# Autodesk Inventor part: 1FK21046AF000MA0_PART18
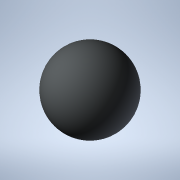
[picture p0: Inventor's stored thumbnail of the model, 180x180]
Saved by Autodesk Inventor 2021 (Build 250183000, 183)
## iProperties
Created: 2025-04
Part Number: 1FK21046AF000MA0_PART18
Material: Generic
Catalog Web Link: www.3dfindit.com
Description: -Servo synchronous motor
Document SubType Name: Modeling
Designer: psAdmin
Mass: 0.137258 g
Surface Area: 1.2868 cm^2
Volume: 0.137258 cm^3
Density: 1 g/cm^3
Appearance: PSOLRGB-212-217-219
Category: PARTsolutions
Title: 1FK21046AF000MA0_PART18
Author: Cadenas PARTsolutions
Comments: Servo synchronous motor
Sending System: PARTsolutions
Preprocessor: ST-DEVELOPER v19.3
PSOL_IDENT_0: {$CADENAS_DATA/23d-libs/siemens_ag/_cat_/1c/1f/1fk21046af000ma0.prj},216 {VTYP=3D},{NB=1FK21046AF000
PSOL_IDENT_1: MA0_PART18},{LINA=1FK21046AF000MA0_PART18},{NN=1FK21046AF000MA0_PART18},{NOPRJ=TRUE},{DATE=19.08.202
PSOL_IDENT_2: 5 14:00:28},{GEOMDATE=30.07.2025 02:02:08},{VERSION=},{LINEID=10},{WBVAR=},{WBNUMERIC=}  {NB=1FK2104
PSOL_IDENT_3: 6AF000MA0_PART18},{LINA=1FK21046AF000MA0_PART18},{KT=DUMMY},{PREVIEW=../../../_pool_/cb/72/p_d211_xx
PSOL_IDENT_4: _00434j.png},{DESCSHORT=SIMOTICS S-1FK2 HD, SINAMICS S210 3AC 400V-480V, 3.2 Nm, 3000 rpm},{DESCLONG=
PSOL_IDENT_5: SIMOTICS S-1FK2 HD servo motor M0=3.2 Nm; PN = 1 kW at nN=3000 rpm (380-480 V); PN = 0.5 kW at nN=15
PSOL_IDENT_6: 00 rpm (200-240 V); degree of protection IP64; cylindrical shaft D19x40mm; absolute encoder 22-bit +
PSOL_IDENT_7: 12-bit multiturn (encoder AM22DQC); with OCC interface; plug size M17, rotatable; SIMOTICS S-1FK2 s
PSOL_IDENT_8: ervomotorfor a wide range of uses in industrial environments. SIMOTICS S‑1FK2 servomotors are compac
PSOL_IDENT_9: t synchronous motors with a high dynamic performance that set themselves apart as a result of their
PSOL_IDENT_10: high power density, degree of protection and overload capability. The motors are available in two va
PSOL_IDENT_11: riants: as High Dynamic variant (highest dynamic performance as a result of the low intrinsic moment
PSOL_IDENT_12: of inertia for applications demanding a high dynamic performance with low moved masses) - and as Co
PSOL_IDENT_13: mpact variant (precise and stable closed-loop control for medium up to large moved masses as a resul
PSOL_IDENT_14: t of a medium intrinsic moment of inertia). SIMOTICSS‑1FK2 servomotors fully exploit their strengths
PSOL_IDENT_15: in a system with the SINAMICSS210 frequency converter and simple connection using the one cable con
PSOL_IDENT_16: nection (OCC). Advantages include the short control and positioning times, fast and precise correcti
PSOL_IDENT_17: on of disturbing quantities as well as stable control with a high dynamic performance. The servo mot
PSOL_IDENT_18: ors can be configured to address a wide range of requirements. For example with and without holding
PSOL_IDENT_19: brake, IP64 or IP65 degree of protection, singleturn or multiturn absolute encoders - to name just a
PSOL_IDENT_20: few. Further, the servomotors are available in different shaft heights extending from 20 to 100. A
PSOL_IDENT_21: shaft sealing ring is available to achieve an IP65 degree of protection and for subsequent mounting
PSOL_IDENT_22: at the motor or as spare part. SIMOTICS - the optimum motor for each and every motion control applic
PSOL_IDENT_23: ation.},{INTNO=195125049666},{SUPPLIERALTNO=1FK2104-6AF00-0MA0},{MANUID=1FK21046AF000MA0},{MANUNAME=
PSOL_IDENT_24: Siemens},{MANUTYPEDESC=Synchronous motor 1FK2-HD 3.2 NM},{AAU732=SIMOTICS},{AAO057=S-1FK2},{AAU734=S
PSOL_IDENT_25: IMOTICS S-1FK2 HD servo motor M0=3.2 Nm; PN = 1 kW at nN=3000 rpm (380-480 V); PN = 0.5 kW at nN=150
PSOL_IDENT_26: 0 rpm (200-240 V); degree of protection IP64; cylindrical shaft D19x40mm; absolute encoder 22-bit +
PSOL_IDENT_27: 12-bit multiturn (encoder AM22DQC); with OCC interface; plug size M17, rotatable;},{AAW338=Synchrono
PSOL_IDENT_28: us motor 1FK2-HD 3.2 NM},{AAO742=SIMOTICS},{AAO663=4042948694374},{NOCUPEROU=1},{PRICEQUANTITY=1},{Q
PSOL_IDENT_29: UANTITYMIN=1},{QUANTITYINT=1},{CTN=85015220},{COO=DE},{AAO676=1FK2104-6AF00-0MA0},{AAO677=Siemens AG
PSOL_IDENT_30: },{ORDERUNIT=C62},{CONTENTUNIT=C62}
NB: 1FK21046AF000MA0_PART18
NT: Servo synchronous motor
NBSYN: $MANUID._PART18
LINA: 1FK21046AF000MA0_PART18
CATALOG: SIEMENS
PREVIEW: ../../../_pool_/cb/72/p_d211_xx_00434j.png
DESCSHORT: SIMOTICS S-1FK2 HD, SINAMICS S210 3AC 400V-480V, 3.2 Nm, 3000 rpm
DESCLONG: SIMOTICS S-1FK2 HD servo motor M0=3.2 Nm; PN = 1 kW at nN=3000 rpm (380-480 V); PN = 0.5 kW at nN=1500 rpm (200-240 V); degree of protection IP64; cylindrical s
INTNO: 195125049666
SUPPLIERALTNO: 1FK2104-6AF00-0MA0
MANUID: 1FK21046AF000MA0
MANUNAME: Siemens
MANUTYPEDESC: Synchronous motor 1FK2-HD 3.2 NM
AAU732: SIMOTICS
AAO057: S-1FK2
AAU734: SIMOTICS S-1FK2 HD servo motor M0=3.2 Nm; PN = 1 kW at nN=3000 rpm (380-480 V); PN = 0.5 kW at nN=1500 rpm (200-240 V); degree of protection IP64; cylindrical s
AAW338: Synchronous motor 1FK2-HD 3.2 NM
AAO742: SIMOTICS
AAO663: 4042948694374.0
NOCUPEROU: 1
PRICEQUANTITY: 1
QUANTITYMIN: 1
QUANTITYINT: 1
CTN: 85015220
COO: DE
ARTICLENO: 1FK21046AF000MA0_PART18
BOMINFO: 1FK21046AF000MA0_PART18
CREATOR: CADENAS GmbH
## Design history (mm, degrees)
feature "2025_04_17_15_39_11_0412"
body "Solid1"
